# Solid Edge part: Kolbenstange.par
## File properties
Username: bmolnar
Dokumentum tartalom típus: 0
Author: bmolnar
Last saved by: bmolnar
Revision: 81
Sűrűség: 0,000 kg/m^3
Pontosság: 0,990
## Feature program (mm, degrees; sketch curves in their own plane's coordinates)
base feature "unnamed BaseFeature 1"
sketch for "unnamed Protrusion 1" plane through (42.5, 0, 0) normal (1, 0, 0) x-axis (0, 0, -1)
  circle centre (0, 0) radius 31.5
extrude "unnamed Protrusion 1" add finite 17.85 along +normal
sketch for "Kihúzás_2" #1 plane through (42.5, 0, 0) normal (1, 0, 0) x-axis (0, 0, -1)
  circle centre (0, 0) radius 8
sketch for "Kihúzás_2" #2 plane through (42.5, 0, 0) normal (1, 0, 0) x-axis (0, 0, -1)
  circle centre (0, 0) radius 31.5
extrude "Kihúzás_2" add finite 11 along -normal
sketch for "Furat_1" plane through (-12, 0, 0.0012) normal (-1, 0, 0) x-axis (0, 0, 1)
  hole centre (-0.0012, 0) bore radius 3.3235
hole "Furat_1" nominal diameter 8 finite  VBottomAngle = 118 deg; ThreadDepth = 14 mm
chamfer "Letörés_1" setback 0.7  SetBackValue2 = 45 deg
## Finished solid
Body 1: solid body, 16 faces, 22 edges, 8 vertices.
  Faces by surface: plane 8, cylinder 5, cone 2, torus 1
  Edges by curve: circle 12, line 6, curve on surface 2, ellipse 2
Bounding box of the edges (mm; curved faces can reach further): 75.350 x 63.000 x 63.000, from (-15, -31.5, -31.5) to (60.35, 31.5, 31.5).
Cylindrical faces by radius (mm): R3.3235 x2, R4.125 x1, R8 x1, R31.5 x1
Conical faces (half-angle, radius in mm at the cone's reference point): 45 deg R4.0235 x1, 59 deg R3.3235 x1
Toroidal faces (ring radius, tube radius in mm): R6.2 r1.8 x1
Planar faces by outward normal: +x 1, +y 1, -x 3, -y 1, oblique 2
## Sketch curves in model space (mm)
circle centre (42.5, 0, 0) radius 31.5
circle centre (42.5, 0, 0) radius 8
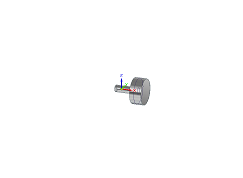
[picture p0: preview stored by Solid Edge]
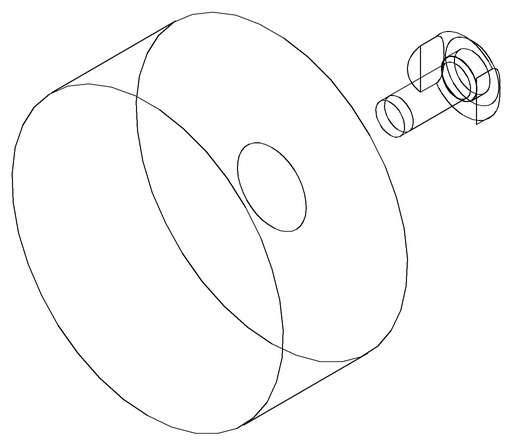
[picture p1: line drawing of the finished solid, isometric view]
